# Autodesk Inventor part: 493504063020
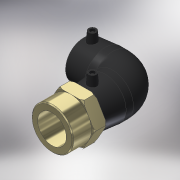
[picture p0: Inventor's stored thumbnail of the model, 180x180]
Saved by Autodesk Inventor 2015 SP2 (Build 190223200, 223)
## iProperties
Created: 2017-06
Part Number: 493504063020
Material: Generic
Description: PLASSON 90° ELBOW FEMALE TRANSITION 63-2''
Document SubType Name: Modeling
Designer: KIM
Mass: 529.599 g
Surface Area: 995.878 cm^2
Volume: 529.599 cm^3
Density: 1 g/cm^3
Appearance: Rubber - Black
Author: KIM
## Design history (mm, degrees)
derived "493504.ipt"
feature "Solid1::493504.ipt"
tag "TaggingFeature1"
body "Solid1"
other parameters: "d2" = 82, "d4" = 43.66667, "d5" = 73.8, "d8" = 168 deg, "d10" = 22.8, "d11" = 7.6, "d29" = 59, "d30" = 15, "d31" = 72.05, "d34" = 5 deg, "d41" = 4, "d42" = 14, "d43" = 0, "d49" = 63, "d50" = 53.55, "d51" = 22.8, "d52" = 57, "d54" = 90 deg, "d57" = 63, "d58" = 57, "d59" = 0, "d61" = 90 deg, "d86" = 3, "d87" = 0, "d93" = 0.1, "d96" = 56.656, "d97" = 48, "d99" = 82, "d100" = 24, "d107" = 12, "d108" = 0, "d109" = 1.89, "d112" = 45 deg, "d113" = 45 deg, "d114" = 3.15, "d_" = 63, "L_" = 161, "L_1" = 57, "D_" = 48, "A_" = 59, "d_2" = 12, "D_1" = 82, "Rp_" = 56.656
